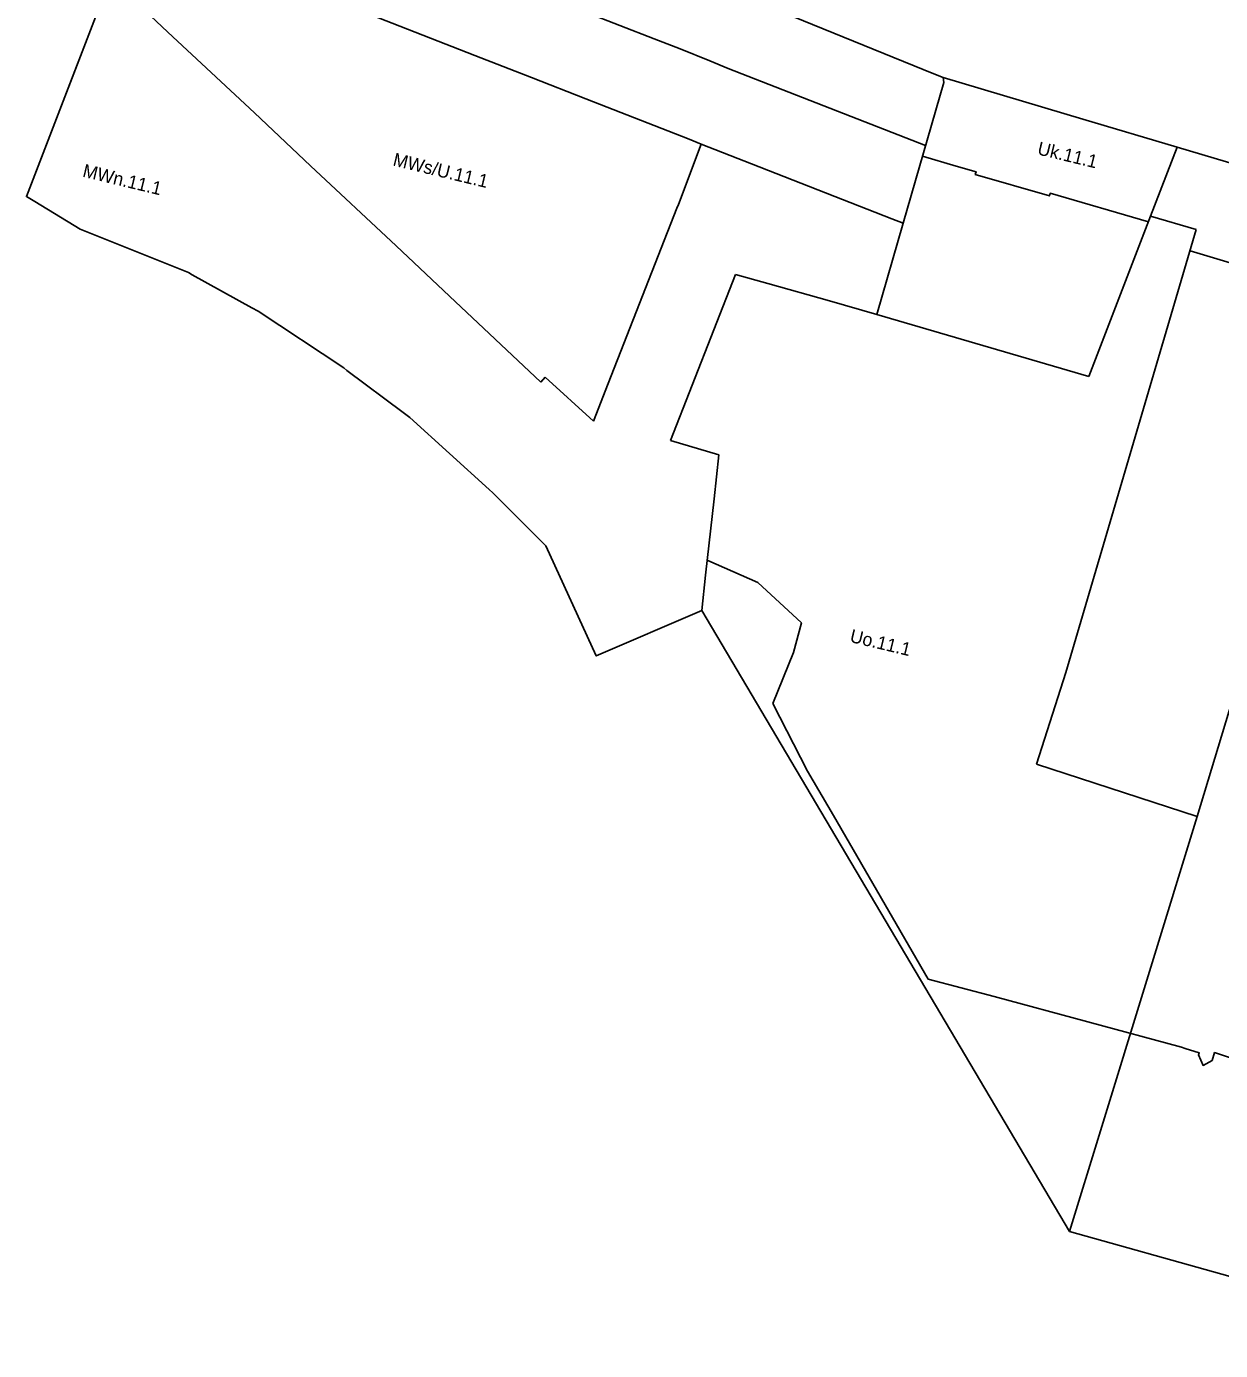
# Model space of a CAD drawing. Extents: x 7429686 to 7432896, y 5547954 to 5550600.
# Drawn here: x 7431071.5 to 7431433.9, y 5548307.1 to 5548709 of the extents above; entities that cross this region are included whole.
import ezdxf

# ---------------------------------------------------------------- set-up
doc = ezdxf.new("R2010")
doc.units = 0
for name, color, linetype in [('granica planu', 7, 'Continuous'), ('linie rozgraniczające', 7, 'Continuous'), ('nieprzekraczalna linia zabudowy', 7, 'Continuous'), ('obowiązująca linia zabudowy', 7, 'Continuous'), ('oznaczenia przeznaczeń', 7, 'Continuous')]:
    doc.layers.add(name, color=color, linetype=linetype)

msp = doc.modelspace()

# ---------------------------------------------------------------- linework, layer by layer
at = {"layer": 'granica planu'}
msp.add_lwpolyline([(7431434.28, 5548330.21), (7431388.06, 5548343.22), (7431276.39, 5548531.74), (7431244.4, 5548517.92), (7431229.12, 5548551.33), (7431226.69, 5548553.76), (7431213, 5548567.41), (7431211.94, 5548568.47), (7431187.8, 5548590.29), (7431185.78, 5548591.8), (7431168.74, 5548604.6), (7431167.76, 5548605.34), (7431141.79, 5548622.57), (7431139.89, 5548623.62), (7431121.74, 5548633.66), (7431120.62, 5548634.28), (7431090.74, 5548646.26), (7431087.73, 5548647.48), (7431073.95, 5548655.85), (7431071.46, 5548657.37), (7431103.57, 5548740.91)], dxfattribs=at)
at = {"layer": 'linie rozgraniczające'}
for points in [[(7431346.81, 5548694.65), (7431264.49, 5548728.2)], [(7431096.99, 5548723.79), (7431071.46, 5548657.37), (7431073.95, 5548655.85), (7431087.73, 5548647.48), (7431090.74, 5548646.26), (7431120.62, 5548634.28), (7431121.74, 5548633.66), (7431139.89, 5548623.62), (7431141.79, 5548622.57), (7431167.76, 5548605.34), (7431168.74, 5548604.6), (7431185.78, 5548591.8), (7431187.8, 5548590.29), (7431211.94, 5548568.47), (7431213, 5548567.41), (7431226.69, 5548553.76), (7431229.12, 5548551.33), (7431244.4, 5548517.92), (7431276.39, 5548531.74)], [(7431114.38, 5548707.25), (7431096.99, 5548723.79)], [(7431207.55, 5548700.22), (7431173.64, 5548713.49)], [(7431140.69, 5548682.75), (7431114.38, 5548707.25)], [(7431224.77, 5548693.48), (7431207.55, 5548700.22)], [(7431241.28, 5548687.01), (7431224.77, 5548693.48)], [(7431349.64, 5548693.48), (7431346.81, 5548694.65)], [(7431349.89, 5548691.96), (7431349.64, 5548693.48)], [(7431349.64, 5548693.48), (7431392.07, 5548680.86)], [(7431337.53, 5548649.28), (7431349.89, 5548691.96)], [(7431272.55, 5548674.75), (7431241.28, 5548687.01)], [(7431157.68, 5548666.68), (7431140.69, 5548682.75)], [(7431392.07, 5548680.86), (7431420.72, 5548672.35)], [(7431276.28, 5548673.29), (7431269.33, 5548655)], [(7431276.28, 5548673.29), (7431272.55, 5548674.75)], [(7431291.54, 5548667.31), (7431276.28, 5548673.29)], [(7431412.66, 5548651.47), (7431420.72, 5548672.35)], [(7431420.72, 5548672.35), (7431473.1, 5548656.83)], [(7431183.67, 5548642.44), (7431157.68, 5548666.68)], [(7431334.07, 5548650.64), (7431291.54, 5548667.31)], [(7431268.89, 5548653.87), (7431248, 5548600.63)], [(7431269.33, 5548655), (7431268.89, 5548653.87)], [(7431329.52, 5548621.62), (7431337.53, 5548649.28)], [(7431337.53, 5548649.28), (7431334.07, 5548650.64)], [(7431412.66, 5548651.47), (7431393.85, 5548602.78)], [(7431426.52, 5548647.4), (7431412.66, 5548651.47)], [(7431386.87, 5548512.87), (7431426.52, 5548647.4)], [(7431199.89, 5548627.17), (7431183.67, 5548642.44)], [(7431266.97, 5548583.33), (7431286.69, 5548633.76)], [(7431286.69, 5548633.76), (7431296.49, 5548630.98)], [(7431296.49, 5548630.98), (7431315.21, 5548625.68)], [(7431227.62, 5548601.07), (7431199.89, 5548627.17)], [(7431315.21, 5548625.68), (7431329.52, 5548621.62)], [(7431393.85, 5548602.78), (7431329.52, 5548621.62)], [(7431228.89, 5548602.6), (7431227.62, 5548601.07)], [(7431243.52, 5548589.2), (7431228.89, 5548602.6)], [(7431248, 5548600.63), (7431243.52, 5548589.2)], [(7431281.62, 5548578.94), (7431266.97, 5548583.33)], [(7431280.15, 5548565.61), (7431281.62, 5548578.94)], [(7431277.58, 5548542.43), (7431280.15, 5548565.61)], [(7431276.39, 5548531.74), (7431277.58, 5548542.43)], [(7431276.39, 5548531.74), (7431388.06, 5548343.22)], [(7431426.79, 5548469.23), (7431441.87, 5548518.94)], [(7431378, 5548485.11), (7431386.87, 5548512.87)], [(7431426.79, 5548469.23), (7431378, 5548485.11)], [(7431397.45, 5548373.8), (7431426.79, 5548469.23)], [(7431388.06, 5548343.22), (7431397.45, 5548373.8)], [(7431388.06, 5548343.22), (7431434.28, 5548330.21), (7431516.52, 5548307.08), (7431518.77, 5548314.69)]]:
    msp.add_lwpolyline(points, dxfattribs=at)
at = {"layer": 'nieprzekraczalna linia zabudowy'}
msp.add_line((7431316.39, 5548469.48), (7431345.16, 5548419.82), dxfattribs=at)
for points in [[(7431278.31, 5548546.91), (7431293.39, 5548540.24), (7431306.64, 5548527.97), (7431304.27, 5548518.96), (7431298, 5548503.51)], [(7431298, 5548503.51), (7431308.56, 5548482.98), (7431316.39, 5548469.48)], [(7431345.16, 5548419.82), (7431365.15, 5548414.54), (7431422.01, 5548399.12), (7431423.1, 5548398.77), (7431427.42, 5548397.44), (7431427.23, 5548396.83), (7431428.6, 5548393.61), (7431431.33, 5548395.16), (7431432.06, 5548397.52), (7431434.73, 5548396.59), (7431454.04, 5548390.41)]]:
    msp.add_lwpolyline(points, dxfattribs=at)
at = {"layer": 'obowiązująca linia zabudowy'}
for points in [[(7431344.36, 5548672.89), (7431284.39, 5548696.28), (7431278.85, 5548698.62), (7431269.85, 5548702.18), (7431261.97, 5548705.24), (7431241.16, 5548713.39), (7431233.79, 5548715.99), (7431127.79, 5548757.61)], [(7431411.98, 5548649.72), (7431382.15, 5548658.39), (7431381.91, 5548657.56), (7431359.42, 5548664.1), (7431359.66, 5548664.91), (7431353.66, 5548666.65), (7431343.42, 5548669.63)], [(7431661.93, 5548587.41), (7431664.76, 5548597.77), (7431619.01, 5548611.26), (7431604.6, 5548615.26), (7431558.56, 5548628.68), (7431555.6, 5548618.44), (7431552.34, 5548607.16), (7431543.4, 5548609.89), (7431542.19, 5548605.72), (7431513.29, 5548614.38), (7431463.15, 5548629.4), (7431424.62, 5548640.94)]]:
    msp.add_lwpolyline(points, dxfattribs=at)

# ---------------------------------------------------------------- texts
at = {"layer": 'oznaczenia przeznaczeń'}
for s, p in [('Uk.11.1', (7431378.04, 5548670.22)), ('MWs/U.11.1', (7431182.43, 5548666.83)), ('MWn.11.1', (7431088.25, 5548663.44)), ('Uo.11.1', (7431321.13, 5548522.22))]:
    msp.add_text(s, height=4, rotation=346.4891, dxfattribs=at).set_placement(p)

doc.saveas('drawing.dxf')
